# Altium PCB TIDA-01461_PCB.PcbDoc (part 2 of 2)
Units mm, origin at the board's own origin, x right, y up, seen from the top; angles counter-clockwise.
Board outline 92.5 x 57.5 mm, 4 copper layers (Top Layer, Mid Layer 1, Mid Layer 2, Bottom Layer), stack 1.54 mm thick; 150 components, 62 nets, 436 pads, 169 vias.
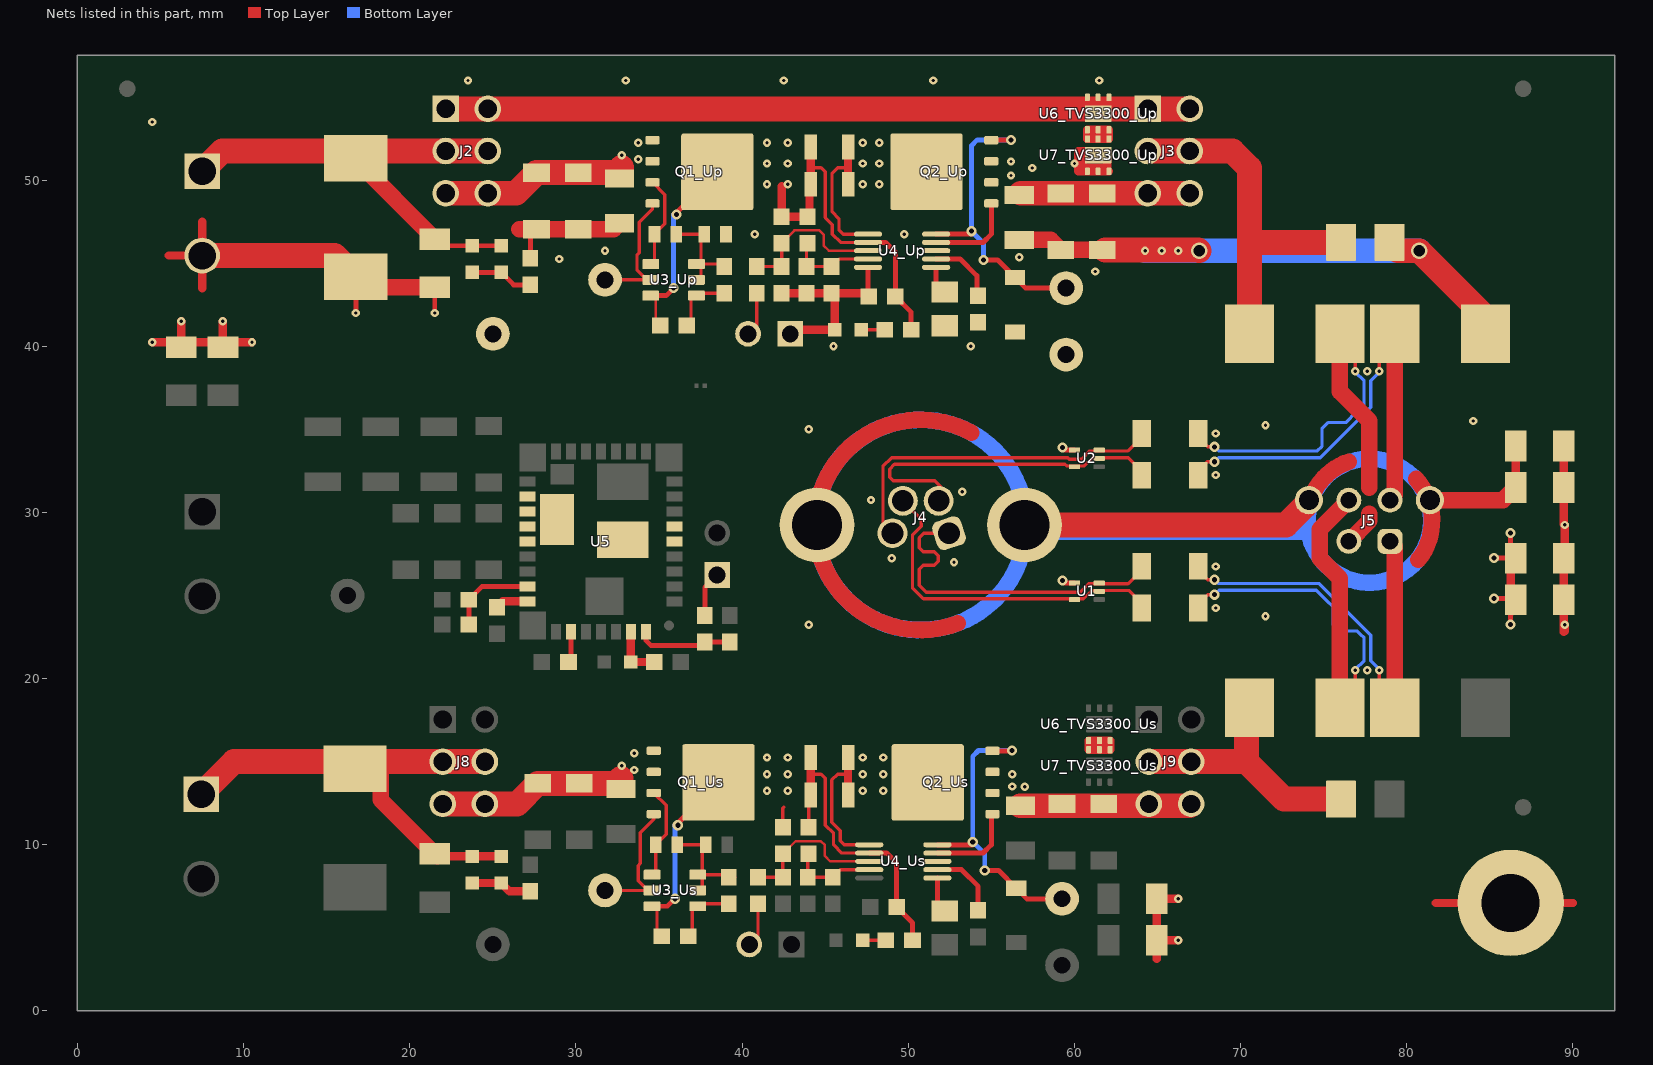
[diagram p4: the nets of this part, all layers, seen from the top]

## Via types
v1: diameter 0.5, hole 0.2, Top Layer to Bottom Layer, 134 vias
v2: diameter 0.61, hole 0.305, Top Layer to Bottom Layer, 15 vias
v3: diameter 0.6, hole 0.3, Top Layer to Bottom Layer, 6 vias
v4: diameter 0.5, hole 0.3, Top Layer to Bottom Layer, tented both sides, 6 vias
v5: diameter 1, hole 0.5, Top Layer to Bottom Layer, 6 vias
v6: diameter 1, hole 0.7, Top Layer to Bottom Layer, 2 vias

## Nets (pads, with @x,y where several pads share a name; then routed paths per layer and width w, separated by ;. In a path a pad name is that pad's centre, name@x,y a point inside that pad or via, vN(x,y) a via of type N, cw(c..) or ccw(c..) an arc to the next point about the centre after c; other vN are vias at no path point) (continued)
GND_Up: C1.1 C2.2 C11.1 C13_Up.2 C14_Up.2 C15_Up.2 C16_Up.2 C17_Up.2 C18_Up.2 C20_Up.2 C21_Up.2 C22_Up.2 D1.2 D8_Up.1 D9_Up.1 D10_Up.2 J1.2 J10_Up.1 L2.1 R1.1 R5.2 R14_Up.1 R15_Up.1 R16_Up.1 TP4.1 TP5.1 U4_Up.5 U7_TVS3300_Up.1 U7_TVS3300_Up.2 U7_TVS3300_Up.3 U7_TVS3300_Up.7@61.425,51.5 | length 97.3
  Top Layer w0.3: v1(16.75,42) D1.2@16.75,42.918 ; D1.2@16.75,44.182 D1.2@17.382,43.55 ; v1(21.5,42) C1.1@21.5,43.55 ; R1.1@27.25,45.3 27.25,47.05 C13_Up.2@27.625,47.05 ; C22_Up.2@47.575,43.2 U4_Up.5@47.575,44.75
  Top Layer w0.5: v1(4.5,40.25) C11.1@6.25,40.25 ; 5.5,45.46 J1.2@7.5,45.46 ; v1(6.25,41.5) C11.1@6.25,40.25 ; 7.5,43.5 J1.2@7.5,45.46 ; 7.5,47.5 J1.2@7.5,45.46 ; R5.2@8.75,39.95 R5.2@8.75,40.25 ; v1(8.75,41.5) R5.2@8.75,40.25 ; v1(10.5,40.25) R5.2@8.75,40.25 ; R14_Up.1@42.375,43.2 C20_Up.2@45.575,43.2 ; J10_Up.1@42.895,40.75 42.895,41 D8_Up.1@45.575,41 C20_Up.2@45.575,43.2 ; C20_Up.2@45.375,43.2 C20_Up.2@45.575,43.2 ; C22_Up.2@47.575,43.2 C20_Up.2@45.575,43.2 ; U7_TVS3300_Up.7@61,51.75 60.225,51.75 60.225,50.75 ; U7_TVS3300_Up.3@62.075,50.525 U7_TVS3300_Up.2@61.425,50.525 U7_TVS3300_Up.1@60.775,50.525 60.225,50.525 60.225,50.75 ; C11.1@6.25,40.25 C11.1@6.25,39.95 C11.1@6.25,40.25 ; C11.1@6.25,40.25 R5.2@8.75,40.25 ; 60.225,50.75 60.5,50.75 ; 60.5,50.75 60.5,51.5 v1(60.875,51.5) U7_TVS3300_Up.7@61.425,51.5 v1(61.975,51.5) 61.975,50.75 60.5,50.75
  Top Layer w1: D1.2@17.382,43.55 C1.1@21.5,43.55 ; 26.6,47.05 C13_Up.2@27.25,47.05 ; C13_Up.2@27.625,47.05 C14_Up.2@30.125,47.05 32.275,47.05 C15_Up.2@32.625,47.4 ; C16_Up.2@56.675,46.4 58.575,46.4 C17_Up.2@59.175,45.8 C18_Up.2@61.675,45.8
  Top Layer w1.5: J1.2@7.5,45.46 15.472,45.46 D1.2@16.75,44.182 ; C18_Up.2@61.85,45.8 67.45,45.8 v6(67.5,45.75) ; C2.2@78.96,46.25 79.46,45.75 v6(80.75,45.75) 84.725,41.775 L2.1@84.725,40.75
  Bottom Layer w1.5: v1(64.25,45.75) v6(80.75,45.75)
  other v1: 45.5,40 53.75,40 61.25,44.5 29,45.25 56.675,45.35 31.75,45.75 65.25,45.75 66.25,45.75 40.75,46.75 49.75,46.75 60,51 4.5,53.5 23.5,56 33,56 42.5,56 51.5,56 61.5,56
IN1_TVS3300_Up: J2.1 J2.2 J3.1 J3.2 U6_TVS3300_Up.1 U6_TVS3300_Up.2 U6_TVS3300_Up.3 U6_TVS3300_Up.7@61.425,54 | length 44.8
  Top Layer w1.5: J2.1@22.155,54.29 J2.2@24.695,54.29 J3.1@64.405,54.29 J3.2@66.945,54.29
  other v1: 60.875,54 61.975,54
NetC19_Up_1: C19_Up.1 R9_Up.1 U3_Up.1 | length 4.4
  Top Layer w0.2: R9_Up.1@36.675,41.25 36.925,41.25 36.925,43.05 U3_Up.1@37.25,43.05 37.25,43.2 C19_Up.1@39.125,43.2
NetC19_Up_2: C19_Up.2 D7_Up.2 D9_Up.2 U3_Up.2 U3_Up.3 | length 6.2
  Top Layer w0.2: D7_Up.2@36.025,46.75 D9_Up.2@37.525,46.75 ; U3_Up.2@37.25,44 37.525,44 U3_Up.3@37.525,44.95 ; D9_Up.2@37.725,46.75 37.525,46.55 U3_Up.3@37.525,44.95 ; C19_Up.2@39.125,44.95 U3_Up.3@37.525,44.95
NetC19_Us_1: C19_Us.1 R9_Us.1 U3_Us.1 | length 4.4
  Top Layer w0.2: R9_Us.1@36.75,4.5 37,4.5 37,6.3 U3_Us.1@37.325,6.3 37.325,6.45 C19_Us.1@39.2,6.45
NetC19_Us_2: C19_Us.2 D7_Us.2 D9_Us.2 U3_Us.2 U3_Us.3 | length 6.8
  Top Layer w0.2: D7_Us.2@36.1,10 37.6,10 U3_Us.3@37.6,8.2 ; U3_Us.2@37.325,7.25 37.6,7.25 U3_Us.3@37.6,8.2 ; U3_Us.3@37.325,8.2 U3_Us.3@37.6,8.2 ; C19_Us.2@39.2,8.05 C19_Us.2@39.551,8.05 ; C19_Us.2@39.2,8.2 U3_Us.3@37.6,8.2
NetC20_Up_1: C20_Up.1 R12_Up.1 R15_Up.2 U4_Up.4 | length 5.2
  Top Layer w0.2: R12_Up.1@43.875,46.15 R15_Up.2@43.875,44.8 C20_Up.1@45.375,44.8 45.825,45.25 U4_Up.4@47.575,45.25
NetC20_Us_1: C20_Us.1 R12_Us.1 R15_Us.2 U4_Us.4 | length 5.2
  Top Layer w0.2: R12_Us.1@43.95,9.4 R15_Us.2@43.95,8.05 C20_Us.1@45.45,8.05 45.9,8.5 U4_Us.4@47.65,8.5
NetC21_Up_1: C21_Up.1 U4_Up.6 | length 1.5
  Top Layer w0.3: C21_Up.1@51.675,43.216 U4_Up.6@51.675,44.75
NetC21_Us_1: C21_Us.1 U4_Us.6 | length 2.2
  Top Layer w0.3: U4_Us.6@51.75,8 51.75,6.466 C21_Us.1@52.2,6.016
NetC22_Up_1: C22_Up.1 Q1_Up.5 Q1_Up.6 Q1_Up.7 Q1_Up.8 Q1_Up.9@38.505,50.5 R7_Up.1 R8_Up.1 R9_Up.2 R10_Up.2 R11_Up.2 R12_Up.2 U3_Up.6 U4_Up.2 | length 33.6
  Top Layer w0.152: U3_Up.6@34.8,43.05 34.8,41.25 R9_Up.2@35.075,41.25
  Top Layer w0.2: 44.25,50.75 44.75,50.75 45,50.5 45,47.75 45.425,47.325 45.425,46.75 45.925,46.25 U4_Up.2@47.575,46.25
  Top Layer w0.3: U3_Up.6@34.5,43.05 34.8,43.05 35.425,43.05 v2(35.875,43.5) ; v2(36.052,47.926) 36,47.977 36,47.995 Q1_Up.9@38.505,50.5 ; U4_Up.2@47.575,46.25 48.625,46.25 49.225,45.65 C22_Up.1@49.225,43 50.175,42.05 R10_Up.2@50.175,41
  Top Layer w0.5: 42.375,49.625 R11_Up.2@42.375,47.8 R12_Up.2@43.925,47.8 44.05,47.925 R8_Up.1@44.05,49.75 ; R8_Up.1@44.125,49.75 R7_Up.1@44.125,52
  Bottom Layer w0.3: v2(35.875,43.5) v2@35.875,47.925 ; v2@35.876,47.926 v2(36.052,47.926)
  other v1: 41.5,49.75 42.75,49.75 41.5,51 42.75,51 41.5,52.25 42.75,52.25
NetC22_Us_1: C22_Us.1 Q1_Us.5 Q1_Us.6 Q1_Us.7 Q1_Us.8 Q1_Us.9@38.58,13.75 R7_Us.1 R8_Us.1 R9_Us.2 R10_Us.2 R11_Us.2 R12_Us.2 U3_Us.6 U4_Us.2 | length 31.7
  Top Layer w0.152: U3_Us.6@34.875,6.3 34.875,4.5 R9_Us.2@35.15,4.5
  Top Layer w0.2: R11_Us.2@42.45,11.05 42.45,12.2 42.5,12.25 ; R12_Us.2@44,11.05 44,12.875 R7_Us.1@44.125,13 ; 44.25,14.25 44.75,14.25 45,14 45,11.184 45.5,10.684 45.5,10 46,9.5 U4_Us.2@47.65,9.5
  Top Layer w0.3: U3_Us.6@34.575,6.3 34.875,6.3 35.5,6.3 v2(35.95,6.75) ; v2(36.127,11.176) 36.075,11.227 36.075,11.245 Q1_Us.9@38.58,13.75 ; U4_Us.2@47.65,9.5 48.7,9.5 49.3,8.9 C22_Us.1@49.3,6.25 50.25,5.3 R10_Us.2@50.25,4.25
  Top Layer w0.5: R7_Us.1@44.125,13 R8_Us.1@44.125,15.25
  Bottom Layer w0.3: v2(35.95,6.75) v2@35.95,11.175 ; v2@35.951,11.176 v2(36.127,11.176)
  other v1: 41.5,13.25 42.75,13.25 41.5,14.25 42.75,14.25 41.5,15.25 42.75,15.25
NetC27_1: C27.1 U5.28 | length 2
  Top Layer w0.5: C27.1@25.25,24.3 25.6,24.65 U5.28@27.075,24.65
NetD2_1: D2.1 D3.2 R1.2 | length 3.8
  Top Layer w0.3: D3.2@23.75,44.45 D2.1@25.5,44.45 26.25,43.7 R1.2@27.25,43.7
NetD4_1: D4.1 D5.2 R6.1 | length 3.7
  Top Layer w0.5: D5.2@23.75,7.7 D4.1@25.5,7.7 26,7.2 R6.1@27.25,7.2
NetD8_Up_2: D8_Up.2 R10_Up.1 | length 1.4
  Top Layer w0.2: D8_Up.2@47.175,41 R10_Up.1@48.575,41
NetD8_Us_2: D8_Us.2 R10_Us.1 | length 1.4
  Top Layer w0.2: D8_Us.2@47.25,4.25 R10_Us.1@48.65,4.25
NetD10_Up_1: D10_Up.1 Q2_Up.4 TP7_Up.1 U4_Up.10 | length 18.9
  Top Layer w0.3: U4_Up.10@51.675,46.75 53.8,46.75 53.8,46.923 v2(53.803,46.925) ; v2(54.525,45.2) 55.362,45.2 D10_Up.1@56.425,44.137 57.062,43.5 TP7_Up.1@59.497,43.496 ; Q2_Up.4@54.995,52.405 56.155,52.405 v2(56.175,52.425)
  Bottom Layer w0.3: v2(54.525,45.2) 54.525,46.203 v2(53.803,46.925) 53.803,52.078 54.15,52.425 v2(56.175,52.425)
NetD10_Us_1: D10_Us.1 Q2_Us.4 TP7_Us.1 U4_Us.10 | length 18.5
  Top Layer w0.3: U4_Us.10@51.75,10 53.875,10 53.875,10.173 v2(53.878,10.175) ; v2(54.6,8.45) 55.437,8.45 D10_Us.1@56.5,7.388 57.138,6.75 58.75,6.75 TP7_Us.1@59.25,6.75 ; Q2_Us.4@55.07,15.655 56.23,15.655 v2(56.25,15.675)
  Bottom Layer w0.3: v2(54.6,8.45) 54.6,9.453 v2(53.878,10.175) 53.878,15.328 54.225,15.675 v2(56.25,15.675)
NetJ10_Up_2: J10_Up.2 R13_Up.1 | length 2.7
  Top Layer w0.2: J10_Up.2@40.355,40.75 40.875,41.27 R13_Up.1@40.875,43.2
NetJ10_Us_2: J10_Us.2 R13_Us.1 | length 2.7
  Top Layer w0.2: J10_Us.2@40.43,4 40.95,4.52 R13_Us.1@40.95,6.45
NetJ11_1: J11.1 R19.1 | length 2.7
  Top Layer w0.3: R19.1@37.75,23.8 37.75,25.48 J11.1@38.5,26.23
NetQ1_Up_4: Q1_Up.4 TP6_Up.1 U3_Up.5 | length 8
  Top Layer w0.2: TP6_Up.1@31.75,44 U3_Up.5@34.25,44 ; U3_Up.5@34.5,44 U3_Up.5@34.25,44 ; Q1_Up.4@34.605,48.595 34.605,48.28 33.8,47.475 33.8,45.625 33.675,45.5 33.675,44.575 U3_Up.5@34.25,44
NetQ1_Us_4: Q1_Us.4 TP6_Us.1 U3_Us.5 | length 8
  Top Layer w0.2: TP6_Us.1@31.75,7.25 U3_Us.5@34.325,7.25 ; U3_Us.5@34.575,7.25 U3_Us.5@34.325,7.25 ; Q1_Us.4@34.68,11.845 34.68,11.53 33.875,10.725 33.875,8.875 33.75,8.75 33.75,7.825 U3_Us.5@34.325,7.25
NetQ2_Up_5: Q2_Up.5 Q2_Up.6 Q2_Up.7 Q2_Up.8 Q2_Up.9@51.095,50.5 R7_Up.2 R8_Up.2 U4_Up.1 | length 8.7
  Top Layer w0.2: 46.25,50.75 45.75,50.75 45.408,50.408 45.408,48.092 45.825,47.675 45.825,47 46.075,46.75 U4_Up.1@47.575,46.75
  Top Layer w0.5: R8_Up.2@46.375,49.75 R7_Up.2@46.375,52
  other v1: 47.25,49.75 48.25,49.75 47.25,51 48.25,51 47.25,52.25 48.25,52.25
NetQ2_Us_5: Q2_Us.5 Q2_Us.6 Q2_Us.7 Q2_Us.8 Q2_Us.9@51.17,13.75 R7_Us.2 R8_Us.2 U4_Us.1 | length 9
  Top Layer w0.2: 46.25,14.25 45.75,14.25 45.4,13.9 45.4,11.35 45.9,10.85 45.9,10.25 46.15,10 U4_Us.1@47.65,10
  Top Layer w0.5: R7_Us.2@46.375,13 R8_Us.2@46.375,15.25
  other v1: 47.25,13.25 48.5,13.25 47.25,14.25 48.5,14.25 47.25,15.25 48.5,15.25
NetR11_Up_1: R11_Up.1 R13_Up.2 R14_Up.2 U4_Up.3 | length 9.3
  Top Layer w0.15: R11_Up.1@42.375,46.2 43.15,46.975 44.65,46.975 44.9,46.725 44.9,46.075 45.225,45.75 U4_Up.3@47.575,45.75
  Top Layer w0.2: R13_Up.2@40.875,44.8 R14_Up.2@42.375,44.8 R11_Up.1@42.375,46.2
NetR11_Us_1: R11_Us.1 R13_Us.2 R14_Us.2 U4_Us.3 | length 9.3
  Top Layer w0.15: R11_Us.1@42.45,9.45 43.225,10.225 44.725,10.225 44.975,9.975 44.975,9.325 45.3,9 U4_Us.3@47.65,9
  Top Layer w0.2: R13_Us.2@40.95,8.05 R14_Us.2@42.45,8.05 R11_Us.1@42.45,9.45
NetR16_Up_2: R16_Up.2 U4_Up.7 | length 4.3
  Top Layer w0.3: U4_Up.7@51.675,45.25 53.125,45.25 54.125,44.25 R16_Up.2@54.125,42.8
NetR16_Us_2: R16_Us.2 U4_Us.7 | length 4.3
  Top Layer w0.3: U4_Us.7@51.75,8.5 53.2,8.5 54.2,7.5 R16_Us.2@54.2,6.05
NetR17_1: R17.1 R21.2 U5.27 | length 5.4
  Top Layer w0.3: R21.2@23.55,23.25 R17.1@23.55,24.75 24.35,25.55 U5.27@27.075,25.55
NetR18_2: R18.2 R19.2 U5.36 | length 5.8
  Top Layer w0.3: U5.36@34.2,22.825 34.2,22.3 34.5,22 37.55,22 R19.2@37.75,22.2 R18.2@39.25,22.2
NetR22_2: R22.2 U5.31 | length 2.1
  Top Layer w0.3: R22.2@29.55,20.75 29.7,20.9 U5.31@29.7,22.825
NetU6_TVS3300_Up_4: U6_TVS3300_Up.4 U6_TVS3300_Up.5 U6_TVS3300_Up.6 U7_TVS3300_Up.4 U7_TVS3300_Up.5 U7_TVS3300_Up.6 | length 5
  Top Layer w0.5: U6_TVS3300_Up.4@60.775,53.025 U6_TVS3300_Up.5@61.425,53.025 U6_TVS3300_Up.6@62.075,53.025 U7_TVS3300_Up.4@62.075,52.475 U7_TVS3300_Up.5@61.425,52.475 U7_TVS3300_Up.6@60.775,52.475 60.75,52.475 60.75,52.95 61.75,52.95 61.75,52.55
NetU6_TVS3300_Us_4: U6_TVS3300_Us.4 U6_TVS3300_Us.5 U6_TVS3300_Us.6 U7_TVS3300_Us.4 U7_TVS3300_Us.5 U7_TVS3300_Us.6 | length 4.9
  Top Layer w0.5: U6_TVS3300_Us.4@60.85,16.275 U6_TVS3300_Us.5@61.5,16.275 U6_TVS3300_Us.6@62.15,16.275 U6_TVS3300_Us.6@62.15,16.2 ; U6_TVS3300_Us.6@62.15,16.2 U7_TVS3300_Us.4@62.15,15.725 U7_TVS3300_Us.5@61.5,15.725 U7_TVS3300_Us.6@60.85,15.725 60.85,16.2 U6_TVS3300_Us.6@62.15,16.2
PE: C5.1 C8.1 C9.1 MH1.1 R2.2 R3.2 R4.2 | length 26.6
  Top Layer w0.5: 64.95,3.125 C9.1@64.95,4.25 ; v1(66.25,4.25) C9.1@64.95,4.25 ; v1(66.25,6.75) R4.2@64.95,6.75 C9.1@64.95,4.25 ; 81.75,6.5 MH1.1@86.25,6.5 ; v1(89.5,23.25) 89.5,22.85 89.45,22.8 C5.1@89.45,24.75 R2.2@89.45,27.25 89.5,27.3 v1(89.5,29.25) 89.45,29.3 C8.1@89.45,31.5 R3.2@89.45,34 R3.2@89.5,33.95 ; 90,6.5 MH1.1@86.377,6.5 ; MH1.1@86.25,6.5 86.25,6.373 86.377,6.373 MH1.1@86.377,6.5 ; MH1.1@86.25,6.5 MH1.1@86.377,6.5
PH: U5.6 U5.7 U5.21 U5.22 U5.23 U5.24 U5.38 U5.41
PWR_in_Up: C13_Up.1 C14_Up.1 C15_Up.1 D7_Up.1 J2.5 J2.6 Q1_Up.1 Q1_Up.2 Q1_Up.3 U3_Up.4 | length 16.8
  Top Layer w0.2: U3_Up.4@34.5,44.95 34.725,45.175 D7_Up.1@34.725,46.75 35.35,47.375 35.35,49.12 Q1_Up.3@34.605,49.865
  Top Layer w1.5: J2.5@22.155,49.21 J2.6@24.695,49.21 26.385,49.21 C13_Up.1@27.625,50.45 C14_Up.1@30.125,50.45 32.45,50.45 32.75,50.75
  other v1: 33.75,51.25 32.75,51.5 33.75,52.25
PWR_in_Us: C13_Us.1 C14_Us.1 C15_Us.1 D7_Us.1 J8.5 J8.6 Q1_Us.1 Q1_Us.2 Q1_Us.3 U3_Us.4 | length 16.9
  Top Layer w0.2: U3_Us.4@34.575,8.2 34.8,8.425 D7_Us.1@34.8,10 35.425,10.625 35.425,12.37 Q1_Us.3@34.68,13.115
  Top Layer w1.5: J8.5@21.98,12.46 J8.6@24.52,12.46 26.46,12.46 C13_Us.1@27.7,13.7 C14_Us.1@30.2,13.7 32.4,13.7 32.7,14
  other v1: 33.5,14.5 32.75,14.75 33.5,15.5
PWRGD: D11.2 R20.1 U5.35 | length 3.2
  Top Layer w0.5: U5.35@33.3,22.825 D11.2@33.3,21 R20.1@34.7,21
RXE_N: C6.2 J4.3 U2.3 | length 20.9
  Top Layer w0.2: J4.3@49.05,28.75 48.475,29.325 48.475,32.775 49,33.3 59.591,33.3 59.691,33.2 60.425,33.2 60.925,33.7 61.49,33.7 63.225,33.7 64.05,34.525 C6.2@64.05,34.75
RXE_P: C3.2 J4.2 U2.2 U2.5 | length 20.9
  Top Layer w0.2: J4.2@51.825,30.7 52,30.875 52,31.5 51.6,31.9 49.1,31.9 48.875,32.125 48.875,32.609 49.166,32.9 59.425,32.9 59.525,32.8 60.591,32.8 61.091,33.3 61.49,33.3 63.25,33.3 64.05,32.5 C3.2@64.05,32.25
RXEP_N: C6.1 J5.3 L1.2 | length 29.4
  Top Layer w0.2: C6.1@67.45,34.75 67.45,34.525 68.025,33.95 v2(68.425,33.95) ; L1.2@75.975,40.75 76.9,39.825 v1(76.9,38.5)
  Top Layer w1: L1.2@75.975,40.75 75.975,37.275 77.75,35.5 77.75,31.5 ; J5.3@76.51,28.26 77.75,29.5 77.75,29.929
  Bottom Layer w0.2: v2(68.425,33.95) 68.675,33.7 74.525,33.7 74.625,33.7 74.892,33.967 74.892,34.508 74.892,35.051 75.254,35.413 75.797,35.413 76.338,35.413 76.972,36.047 77.425,36.5 77.425,37.922 76.9,38.447 v1(76.9,38.5)
RXEP_P: C3.1 J5.2 L2.2 | length 27.4
  Top Layer w0.2: C3.1@67.45,32.25 67.45,32.5 68,33.05 v2(68.425,33.05) ; v1(78.35,38.5) 78.35,39.825 L2.2@79.275,40.75
  Top Layer w1: J5.2@78.99,30.74 79.275,31.025 L2.2@79.275,40.75
  Bottom Layer w0.2: v2(68.425,33.05) 68.675,33.3 74.791,33.3 77.825,36.334 77.825,37.922 78.35,38.447 v1(78.35,38.5)
Shield: C8.2 J4.S1 J4.S2 J5.S1 J5.S2 R3.1 | length 140.5
  Top Layer w0.5: C8.2@86.55,31.5 R3.1@86.55,34
  Top Layer w1: J4.S2@44.425,29.201 ccw(c50.75,29.25) 52.971,23.328 ; J4.S2@44.425,29.306 cw(c50.75,29.25) 53.779,34.803 ; J5.S2@74.046,30.187 cw(c77.75,29.5) 74.184,30.715 cw(c77.75,29.5) 76.508,33.057 ; 80.56,32.009 cw(c77.75,29.5) 80.699,27.156 ; J5.S1@81.39,30.74 85.79,30.74 C8.2@86.55,31.5
  Top Layer w1.5: J4.S1@57,29.25 72.719,29.25 J5.S2@74.184,30.715
  Bottom Layer w1: J4.S1@56.25,29.25 J4.S1@56.4,29.25 ; J4.S1@57.072,29.441 ccw(c50.75,29.25) J4.S1@57.075,29.194 ; 81.475,29.5 ccw(c77.75,29.5) 81.475,29.5
  Bottom Layer w1.5: J4.S1@56.6,29.1 57.073,29.1 73.9,29.1
TXE_N: C7.2 J4.4 U1.2 U1.5 | length 20.8
  Top Layer w0.2: J4.4@49.675,30.7 50.775,29.6 50.775,29.158 50.25,28.633 50.25,25.459 50.909,24.8 52.3,24.8 59.96,24.8 U1.5@60.01,24.75 60.06,24.8 60.525,24.8 61.025,25.3 63.3,25.3 64.05,24.55 C7.2@64.05,24.25
TXE_P: C4.2 J4.1 U1.3 | length 20.8
  Top Layer w0.2: J4.1@52.45,28.75 50.933,28.75 50.65,28.467 50.65,28.35 50.65,27.865 50.89,27.625 51.56,27.625 51.8,27.385 51.8,27.065 51.56,26.825 50.89,26.825 50.65,26.585 50.65,26.025 50.65,25.625 51.075,25.2 52.466,25.2 60.359,25.2 60.859,25.7 63.225,25.7 64.05,26.525 C4.2@64.05,26.75
TXEP_N: C7.1 J5.4 L4.2 | length 30.9
  Top Layer w0.2: C7.1@67.45,24.25 67.45,24.475 68.025,25.05 v2(68.425,25.05) ; L4.2@75.975,18.25 76.9,19.175 v1(76.9,20.5)
  Top Layer w1: L4.2@75.975,18.25 75.975,26.025 74.75,27.25 74.75,28.98 J5.4@76.51,30.74
  Bottom Layer w0.2: v2(68.425,25.05) 68.7,25.325 74.55,25.325 75.188,24.687 75.564,24.311 75.564,23.768 75.562,23.767 75.562,23.223 75.924,22.861 76.467,22.861 76.469,22.863 77.012,22.863 77.193,22.682 77.425,22.45 77.425,21.078 76.9,20.553 v1(76.9,20.5)
TXEP_P: C4.1 J5.1 L3.2 | length 27.3
  Top Layer w0.2: C4.1@67.45,26.75 67.45,26.525 68.025,25.95 v2(68.425,25.95) ; v1(78.35,20.5) 78.35,19.175 L3.2@79.275,18.25
  Top Layer w1: J5.1@78.99,28.26 79.275,27.975 L3.2@79.275,18.25
  Bottom Layer w0.2: v2(68.425,25.95) 68.65,25.725 74.716,25.725 77.825,22.616 77.825,21.078 78.35,20.553 v1(78.35,20.5)
UP: C1.2 D1.1 D2.2 D3.1 J1.1 J2.3 J2.4 | length 28.7
  Top Layer w0.3: C1.2@21.5,46.45 21.9,46.05 D3.1@23.75,46.05 D2.2@25.5,46.05
  Top Layer w1: D1.1@16.75,51.319 16.75,51.2 C1.2@21.5,46.45
  Top Layer w1.5: J1.1@7.5,50.54 8.71,51.75 J2.3@22.155,51.75 J2.4@24.695,51.75
Up_InOut: C2.1 J3.3 J3.4 L1.1 | length 22
  Top Layer w1.5: J3.3@64.405,51.75 J3.4@66.945,51.75 69.5,51.75 70.525,50.725 70.525,46.25 ; L1.1@70.525,40.75 70.525,46.25 ; C2.1@76.04,46.25 70.525,46.25
UP_PGD: U4_Up.8
UP_PROTECTED: C16_Up.1 C17_Up.1 C18_Up.1 J3.5 J3.6 Q2_Up.1 Q2_Up.2 Q2_Up.3 U4_Up.9 | length 15.5
  Top Layer w0.3: U4_Up.9@51.675,46.25 54.5,46.25 55,46.75 55,48.59 Q2_Up.1@54.995,48.595
  Top Layer w1.5: C16_Up.1@56.785,49.21 J3.5@64.405,49.21 J3.6@66.945,49.21
  other v1: 56.175,50.275 57.45,50.725 56.175,51.125
US: C12.1 D4.2 D5.1 D6.2 J7.1 J8.3 J8.4 | length 28.6
  Top Layer w0.5: C12.1@21.5,9.3 21.65,9.3 D4.2@25.5,9.3
  Top Layer w1: D6.2@18.25,14.568 18.25,12.7 C12.1@21.5,9.45 C12.1@21.65,9.3
  Top Layer w1.5: J7.1@7.45,13.04 9.41,15 J8.3@21.98,15 J8.4@24.52,15
Us_InOut: C10.1 J9.3 J9.4 L4.1 | length 15.8
  Top Layer w1.5: J9.3@64.48,15 J9.4@67.02,15 70.35,15 ; L4.1@70.525,18.25 70.35,18.075 70.35,15 ; C10.1@76.04,12.75 72.6,12.75 70.35,15
US_PGD: U4_Us.8
Us_protected: C16_Us.1 C17_Us.1 C18_Us.1 J9.5 J9.6 Q2_Us.1 Q2_Us.2 Q2_Us.3 U4_Us.9 | length 15.6
  Top Layer w0.3: U4_Us.9@51.75,9.5 54.5,9.5 55,10 55,11.775 Q2_Us.1@55.07,11.845
  Top Layer w1.5: C16_Us.1@56.75,12.35 66.91,12.35 J9.6@67.02,12.46
  other v1: 57,13.5 56.25,13.504 56.25,14.25
VGND: C5.2 R2.1 U1.4 U2.4 | length 9.3
  Top Layer w0.3: v3(59.275,25.9) 59.425,25.75 U1.4@60.01,25.75 ; v3(59.275,33.9) 59.425,33.75 U2.4@60.01,33.75 ; v3@85.101,27.351 85.203,27.25 v3(85.25,27.25) 86.25,27.25 R2.1@86.3,27.25 ; v3(85.25,24.832) C5.2@86.25,24.832 ; v3(86.25,23.25) C5.2@86.25,24 ; R2.1@86.25,27.55 v3(86.25,28.75)
  Top Layer w0.5: C5.2@86.25,24 86.25,24.832 86.25,27.25 R2.1@86.25,27.55
  other v1: 77.625,20.5 44,23.25 71.5,23.75 68.5,24.25 68.5,26.75 52.75,27 49,27.25 47.75,30.75 53.25,31.25 68.5,32.25 68.5,34.75 44,35 71.5,35.25 84,35.5 77.625,38.5
pads on no net: FID1.1 FID2.1 FID3.1 LBL1.0 Q1_Up.9@37.245,49.03 Q1_Up.9@37.245,50.5 Q1_Up.9@37.245,51.97 Q1_Up.9@38.925,49.03 Q1_Up.9@38.925,50.5 Q1_Up.9@38.925,51.97 Q1_Us.9@37.32,12.28 Q1_Us.9@37.32,13.75 Q1_Us.9@37.32,15.22 Q1_Us.9@39,12.28 Q1_Us.9@39,13.75 Q1_Us.9@39,15.22 Q2_Up.9@50.675,49.03 Q2_Up.9@50.675,50.5 Q2_Up.9@50.675,51.97 Q2_Up.9@52.355,49.03 Q2_Up.9@52.355,50.5 Q2_Up.9@52.355,51.97 Q2_Us.9@50.75,12.28 Q2_Us.9@50.75,13.75 Q2_Us.9@50.75,15.22 Q2_Us.9@52.43,12.28 Q2_Us.9@52.43,13.75 Q2_Us.9@52.43,15.22 SH-J1.0 SH-J2.0 SH-J3.0 SH-J4.0 SH-J5.0 SH-J6.0 SH-J7.0 SH-J8.0 SH-J9_Up.0 SH-J9_Us.0 SH-J10.0 U1.1 U2.1 U5.2 U5.3 U5.25 U6_TVS3300_Up.7@60.975,54 U6_TVS3300_Up.7@61.875,54 U6_TVS3300_Us.7@61.05,17.25 U6_TVS3300_Us.7@61.95,17.25 U7_TVS3300_Up.7@60.975,51.5 U7_TVS3300_Up.7@61.875,51.5 U7_TVS3300_Us.7@61.05,14.75 U7_TVS3300_Us.7@61.95,14.75
copper on no net:
  other v5: 86.25,4.025 84.107,5.263 88.393,5.263 84.107,7.737 88.393,7.737 86.25,8.975

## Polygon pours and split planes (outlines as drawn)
RXEP_N on Top Layer "TOP_LAYER_RXEP_N_P233" (solid, pour order 233): 77.247,29.75 77.325,30.538 77.325,31.038 77.247,31.75 78.251,31.75 78.125,31.038 78.125,30.538 78.251,29.75
PE on Top Layer "TOP_LAYER_PE_P257" (solid, remove dead copper, pour order 257): 64.5,2.5 64.25,2.75 64.25,7.75 82,7.75 84.5,10.25 88.25,10.25 88.75,10.75 88.75,35 90.25,35 90.5,34.75 90.5,2.75 90.25,2.5
VGND on Top Layer "TOP_LAYER_VGND_P256" (solid, remove dead copper, pour order 256): 69.75,11.25 70,11 87,11.001 87.25,11.25 87.25,48 87,48.25 70,48.25 69.75,48 69.75,37 69.5,36.75 42.75,36.75 42.5,36.5 42.5,22 42.75,21.75 69.5,21.75 69.75,21.5
AGND on Top Layer "TOP_LAYER_AGND_P244" (solid, remove dead copper, pour order 244): 27.75,24.5 27.75,27.75 36.5,27.75 36.5,29.75 37.75,29.75 37.75,37.75 41,37.75 41.25,37.5 41.25,27.75 41.25,22.25 26.5,22.25 26.5,24.5
PH on Top Layer "TOP_LAYER_PH_P241" (solid, pour order 241): 36.5,27.75 34.5,27.75 34.5,27.25 31.25,27.25 31.25,28 26.5,28 26.5,31.25 30,31.25 30,29.5 36.5,29.5
BUCK_OUT on Top Layer "TOP_LAYER_BUCK_OUT_P245" (solid, remove dead copper, pour order 245): 31.25,30.75 31.25,34.5 25.75,34.5 25.5,34.75 25.5,35.75 36.5,35.75 36.5,31.5 34.5,31.5 34.5,30.75 31.37,30.75 31.37,30.89
PWR_in_Us on Top Layer "TOP_LAYER_PWR_IN_US_P234" (solid, remove dead copper, pour order 234): 35.25,12.75 31.75,12.75 31.75,14.25 32.75,16 35.25,16
NetC22_Us_1 on Top Layer "TOP_LAYER_NETC22_US_1_P235" (solid, remove dead copper, pour order 235): 39.75,11.5 41.5,11.5 41.5,11.75 44.5,11.75 44.5,16 39.75,16
NetQ2_Us_5 on Top Layer "TOP_LAYER_NETQ2_US_5_P236" (solid, remove dead copper, pour order 236): 50,11.5 46,11.5 46,16 50,16
Us_protected on Top Layer "TOP_LAYER_US_PROTECTED_P237" (solid, remove dead copper, pour order 237): 54.5,14.75 54.5,11.5 55.525,11.5 55.775,11.75 58.25,11.75 58.25,14.5 58,14.75
UP_PROTECTED on Top Layer "TOP_LAYER_UP_PROTECTED_P242" (solid, remove dead copper, pour order 242): 54.5,51.5 54.5,48.25 55.525,48.25 55.775,48.5 58.25,48.5 58.25,51.25 58,51.5
NetQ2_Up_5 on Top Layer "TOP_LAYER_NETQ2_UP_5_P240" (solid, remove dead copper, pour order 240): 50,48.25 46,48.25 46,52.75 50,52.75
NetC22_Up_1 on Top Layer "TOP_LAYER_NETC22_UP_1_P239" (solid, remove dead copper, pour order 239): 39.75,48.25 41.5,48.25 41.5,48.5 44.5,48.5 44.5,52.75 39.75,52.75
PWR_in_Up on Top Layer "TOP_LAYER_PWR_IN_UP_P238" (solid, remove dead copper, pour order 238): 35.25,49.5 31.75,49.5 31.75,51 32.75,52.75 35.25,52.75
GND on Top Layer "TOP_LAYER_GND_P243" (solid, remove dead copper, pour order 243): 14,29.492 14,31.25 14,32.25 26.25,32.25 26.25,34.25 31.25,34.25 31.25,30.75 34.5,30.75 34.5,31.25 36.5,31.25 36.5,37.75 37.75,37.75 37.75,29.753 37.5,29.492 30.008,29.492 30,31.25 26.5,31.25 26.5,29.492
GND on Top Layer "TOP_LAYER_GND_P254" (solid, remove dead copper, pour order 254): 2.75,37.75 2.5,37.498 2.5,22.25 2.5,2.75 2.75,2.5 62.25,2.5 62.5,2.75 62.5,19.75 62.25,20 41.25,20 41.25,37.498 41,37.75
GND_Up on Top Layer "TOP_LAYER_GND_UP_P255" (solid, remove dead copper, pour order 255): 2.75,39.25 62.25,39.25 62.5,39.508 62.5,56.25 62.25,56.5 2.75,56.5 2.5,56.25 2.5,39.5
GND on Mid Layer 1 "MID_LAYER_1_GND_P266" (solid, remove dead copper, pour order 266): 2.75,37.75 2.5,37.498 2.5,22.25 2.5,2.75 2.75,2.5 62.25,2.5 62.5,2.75 62.5,19.75 62.25,20 41.25,20 41.25,37.498 41,37.75
PE on Mid Layer 1 "MID_LAYER_1_PE_P269" (solid, remove dead copper, pour order 269): 64.5,2.5 64.25,2.75 64.25,7.5 64.5,7.75 82,7.75 84.5,10.25 88.25,10.25 88.75,10.75 88.75,34.75 89,35 90.25,35 90.5,34.75 90.5,2.75 90.25,2.5
VGND on Mid Layer 1 "MID_LAYER_1_VGND_P268" (solid, remove dead copper, pour order 268): 69.75,11.25 70,11 87,11.001 87.25,11.25 87.25,48 87,48.25 70,48.25 69.75,48 69.75,37 69.5,36.75 42.75,36.75 42.5,36.5 42.5,22 42.75,21.75 69.5,21.75 69.75,21.5
GND_Up on Mid Layer 1 "MID_LAYER_1_GND_UP_P267" (solid, remove dead copper, pour order 267): 2.75,39.25 62.25,39.25 62.5,39.508 62.5,56.25 62.25,56.5 2.75,56.5 2.5,56.25 2.5,39.5
GND on Mid Layer 2 "MID_LAYER_2_GND_P262" (solid, remove dead copper, pour order 262): 2.75,37.75 2.5,37.498 2.5,22.25 2.5,2.75 2.75,2.5 62.25,2.5 62.5,2.75 62.5,19.75 62.25,20 41.25,20 41.25,37.498 41,37.75
PE on Mid Layer 2 "MID_LAYER_2_PE_P265" (solid, remove dead copper, pour order 265): 64.5,2.5 64.25,2.75 64.25,7.5 64.5,7.75 82,7.75 84.5,10.25 88.25,10.25 88.75,10.75 88.75,34.75 89,35 90.25,35 90.5,34.75 90.5,2.75 90.25,2.5
VGND on Mid Layer 2 "MID_LAYER_2_VGND_P264" (solid, remove dead copper, pour order 264): 69.75,11.25 70,11 87,11.001 87.25,11.25 87.25,48 87,48.25 70,48.25 69.75,48 69.75,37 69.5,36.75 42.75,36.75 42.5,36.5 42.5,22 42.75,21.75 69.5,21.75 69.75,21.5
GND_Up on Mid Layer 2 "MID_LAYER_2_GND_UP_P263" (solid, remove dead copper, pour order 263): 2.75,39.25 62.25,39.25 62.5,39.508 62.5,56.25 62.25,56.5 2.75,56.5 2.5,56.25 2.5,39.5
GND on Bottom Layer "BOTTOM_LAYER_GND_P258" (solid, remove dead copper, pour order 258): 2.75,37.75 2.5,37.498 2.5,22.25 2.5,2.75 2.75,2.5 62.25,2.5 62.5,2.75 62.5,19.75 62.25,20 41.25,20 41.25,37.498 41,37.75
PE on Bottom Layer "BOTTOM_LAYER_PE_P261" (solid, remove dead copper, pour order 261): 64.5,2.5 64.25,2.75 64.25,7.5 64.5,7.75 82,7.75 84.5,10.25 88.25,10.25 88.75,10.75 88.75,34.75 89,35 90.25,35 90.5,34.75 90.5,2.75 90.25,2.5
VGND on Bottom Layer "BOTTOM_LAYER_VGND_P260" (solid, remove dead copper, pour order 260): 69.75,11.25 70,11 87,11.001 87.25,11.25 87.25,48 87,48.25 70,48.25 69.75,48 69.75,37 69.5,36.75 42.75,36.75 42.5,36.5 42.5,22 42.75,21.75 69.5,21.75 69.75,21.5
GND_Up on Bottom Layer "BOTTOM_LAYER_GND_UP_P259" (solid, remove dead copper, pour order 259): 2.75,39.25 62.25,39.25 62.5,39.508 62.5,56.25 62.25,56.5 2.75,56.5 2.5,56.25 2.5,39.5
PWR_in_Us on Bottom Layer "BOTTOM_LAYER_PWR_IN_US_P249" (solid, remove dead copper, pour order 249): 35.25,12.75 31.75,12.75 31.75,14.25 32.75,16 35.25,16
NetC22_Us_1 on Bottom Layer "BOTTOM_LAYER_NETC22_US_1_P248" (solid, remove dead copper, pour order 248): 39.75,11.5 41.5,11.5 41.5,11.75 44.5,11.75 44.5,16 39.75,16
NetQ2_Us_5 on Bottom Layer "BOTTOM_LAYER_NETQ2_US_5_P247" (solid, remove dead copper, pour order 247): 50,11.5 46,11.5 46,16 50,16
Us_protected on Bottom Layer "BOTTOM_LAYER_US_PROTECTED_P246" (solid, remove dead copper, pour order 246): 54.5,14.75 54.5,11.5 55.525,11.5 55.775,11.75 58.25,11.75 58.25,14.5 58,14.75
UP_PROTECTED on Bottom Layer "BOTTOM_LAYER_UP_PROTECTED_P253" (solid, remove dead copper, pour order 253): 54.5,51.5 54.5,48.25 55.525,48.25 55.775,48.5 58.25,48.5 58.25,51.25 58,51.5
NetQ2_Up_5 on Bottom Layer "BOTTOM_LAYER_NETQ2_UP_5_P252" (solid, remove dead copper, pour order 252): 50,48.25 46,48.25 46,52.75 50,52.75
NetC22_Up_1 on Bottom Layer "BOTTOM_LAYER_NETC22_UP_1_P251" (solid, remove dead copper, pour order 251): 39.75,48.25 41.5,48.25 41.5,48.5 44.5,48.5 44.5,52.75 39.75,52.75
PWR_in_Up on Bottom Layer "BOTTOM_LAYER_PWR_IN_UP_P250" (solid, remove dead copper, pour order 250): 35.25,49.5 31.75,49.5 31.75,51 32.75,52.75 35.25,52.75

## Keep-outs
Keep-Out Layer:
  the board outline again, w0.5
  text ".Layer_Name" at 14.656,-21.806 h1.52

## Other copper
Top Layer:
  region net PE: 70,7.5 70,2.75 80,2.75 80,7.5
  pour cut-out: 12.75,22.25 41.5,22.25 41.5,20 41.25,19.75 12.75,19.75 12.5,20 12.5,22
  pour cut-out: 2.25,22.25 2.5,22.5 2.75,22.25 9.75,22.25 10,22 10,20 9.75,19.75 2.75,19.75 2.5,19.5 2.25,19.75
  text ".Layer_Name" at 14.656,-21.806 h1.52
Mid Layer 1:
  pour cut-out: 2.5,22.25 10,22.25 10,19.75 2.5,19.75
  pour cut-out: 12.5,22.25 41.5,22.25 41.5,19.75 12.5,19.75
  text ".Layer_Name" at 14.656,-21.806 h1.52
Mid Layer 2:
  pour cut-out: 2.5,22.25 10,22.25 10,19.75 2.5,19.75
  pour cut-out: 12.5,22.25 41.5,22.25 41.5,19.75 12.5,19.75
  text ".Layer_Name" at 14.656,-21.806 h1.52
Bottom Layer:
  pour cut-out: 2.5,22.25 10,22.25 10,19.75 2.5,19.75
  pour cut-out: 12.5,22.25 41.5,22.25 41.5,19.75 12.5,19.75
  text ".Layer_Name" at 14.656,-21.806 h1.52

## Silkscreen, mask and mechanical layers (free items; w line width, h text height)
Top Overlay:
  rectangle: 82.38,45.5 90,48.04
  lines w0.2: 0.75,3.75 1.15,2.55 ; 0.75,54.35 1.15,55.55 ; 0.95,2.55 1.35,2.55 ; 0.95,55.55 1.35,55.55 ; 1.15,24.897 1.15,2.55 ; 1.15,33.203 1.15,55.55 ; 1.55,3.75 1.15,2.55 ; 1.55,54.35 1.15,55.55 ; 2.5,1.3 2.5,1.7 ; 3.7,1.1 2.5,1.5 ; 3.7,1.9 2.5,1.5 ; 42.347,1.5 2.5,1.5 ; 50.653,1.5 90.5,1.5 ; 89.3,1.1 90.5,1.5 ; 89.3,1.9 90.5,1.5 ; 90.5,1.3 90.5,1.7
  text "TIDA-01461" at 73.5,54.75 h2
  text "24V Up" at 4.25,54 h2
  text "up to 3A current / use 2 jumpers" at 12,54 h1.2
  text "G-Q1" at 30.5,41.5 h1.2
  text "GNDp" at 4.25,41.25 h2
  text "G-Q2" at 58.5,41.25 h1.2
  text "J10 set: UVLO 22.5V - 23.5V / J10 open: UVLO 20.0V - 21.0V" at 40,37.25 h1.2
  text "5V (Us)" at 4.25,33.5 h2
  text "J11 set : 5V / J11 open: 12V" at 40,30.5 h1.2 r90
  text "53 (mm)" at 1.95,25.151 h1.2 r90
  text "GNDs" at 4.25,20.5 h2
  text "EtherCAT <=> EtherCAT P" at 46.25,20.25 h2
  text "24V Us" at 4.25,16.5 h2
  text "up to 3A current / use 2 jumpers" at 11.75,16.25 h1.2
  text "G-Q1" at 30.5,4.75 h1.2
  text "G-Q2" at 58,4.5 h1.2
  text "GNDs" at 4.25,3.5 h2
  text "88 (mm)" at 42.601,0.7 h1.2
  text ".Layer_Name" at 14.656,-21.806 h1
Bottom Overlay:
  text ".Layer_Name" at 14.656,-21.806 h1.52
Top Paste:
  text ".Layer_Name" at 14.656,-21.806 h1.52
Bottom Paste:
  text ".Layer_Name" at 14.656,-21.806 h1.52
Top Solder:
  text ".Layer_Name" at 14.656,-21.806 h1.52
  text ".Layer_Name" at 14.656,-21.806 h1.52
Bottom Solder:
  text ".Layer_Name" at 14.656,-21.806 h1.52
Drill Guide:
  text ".Layer_Name" at 14.656,-21.806 h1.52
M1 Board Outline:
  lines w0.254: 92.5,0 92.5,57.5
  lines w0.5: 0,0 0,57.5 92.5,57.5 92.5,0 0,0
  text ".Layer_Name" at 14.656,-21.806 h1.52
M2 Board Dimensions:
  lines w0.254: -3,1.5 -2.492,-0.024 ; -3,55.952 -2.492,57.476 ; -2.746,-0.024 -2.238,-0.024 ; -2.746,57.476 -2.238,57.476 ; -2.492,22.226 -2.492,-0.024 ; -2.492,35.226 -2.492,57.476 ; -1.984,1.5 -2.492,-0.024 ; -1.984,55.952 -2.492,57.476 ; -0.024,-2.512 -0.024,-2.004 ; 1.5,-2.766 -0.024,-2.258 ; 1.5,-1.75 -0.024,-2.258 ; 39.726,-2.258 -0.024,-2.258 ; 52.726,-2.258 92.476,-2.258 ; 90.952,-2.766 92.476,-2.258 ; 90.952,-1.75 92.476,-2.258 ; 92.476,-2.512 92.476,-2.004
  text "57.5 (mm)" at -1.578,22.48 h1.52 r90
  text "92.5 (mm)" at 39.98,-3.172 h1.52
  text ".Layer_Name" at 14.656,-21.806 h1.52
M3 3D STEP Top:
  text ".Layer_Name" at 14.656,-21.806 h1.52
M4 3D STEP Bottom:
  text ".Layer_Name" at 14.656,-21.806 h1.52
M5 Assembly Top:
  lines w0.254: -7.417,-23.626 160.223,-23.626 ; -7.417,-18.462 160.274,-18.462 ; -7.417,-13.297 -7.417,-28.791 94.31,-28.791 160.274,-28.791 160.274,-13.297 -7.404,-13.297 -7.404,-28.791 32.614,-28.791 ; 55.194,-28.791 55.194,-13.297 ; 87.376,-18.462 87.376,-13.297 ; 108.712,-18.462 108.712,-13.297 ; 124.511,-28.956 124.511,-23.804
  text "COMPONENTS MARKED 'DNP' SHOULD NOT BE POPULATED." at 29.299,-8.09 h1.52
  text "ASSEMBLY VARIANT:" at 29.286,-11.024 h1.52
  text ".VariantName" at 55.601,-11.024 h1.52
  text "PCB VIEWED FROM TOP SIDE" at -5.804,-16.654 h1.52
  text "BOARD #:" at 57.099,-16.654 h1.52
  text ".PRJ_Number" at 70.955,-16.654 h1.52
  text "REV:" at 92.405,-16.654 h1.52
  text ".PCB_Rev" at 99.809,-16.654 h1.52
  text "SVN REV:" at 113.69,-16.654 h1.52
  text ".VersionControl_RevNumber" at 126.543,-16.654 h1.52
  text "TID #:" at 57.099,-21.819 h1.52
  text ".TID" at 70.955,-21.819 h1.52
  text "PLOT NAME =" at -5.804,-27.034 h1.52
  text ".plot_File_Name" at 14.656,-27.034 h1.52
  text "GENERATED    :" at 57.15,-27.034 h1.52
  text ".Print_Date" at 79.235,-27.034 h1.52
  text ".Print_Time" at 97.752,-27.034 h1.52
  text "TEXAS INSTRUMENTS" at 129.87,-27.034 h1.52
M6 Assembly Bottom:
  lines w0.254: -7.429,-18.474 160.261,-18.474 ; -7.379,-23.639 160.261,-23.639 ; 28.334,-28.969 28.334,-23.817 ; 44.133,-18.474 44.133,-13.31 ; 65.468,-18.474 65.468,-13.31 ; 97.65,-28.804 97.65,-13.31 ; 120.231,-28.804 160.249,-28.804 160.249,-13.31 -7.429,-13.31 -7.429,-28.804 58.534,-28.804 160.261,-28.804 160.261,-13.31
  text "COMPONENTS MARKED 'DNP' SHOULD NOT BE POPULATED." at 154.991,-8.077 h1.52
  text ".VariantName" at 128.473,-11.024 h1.52
  text "ASSEMBLY VARIANT:" at 154.864,-11.024 h1.52
  text ".VersionControl_RevNumber" at 26.302,-16.667 h1.52
  text "SVN REV:" at 39.154,-16.667 h1.52
  text ".PCB_Rev" at 53.035,-16.667 h1.52
  text "REV:" at 60.439,-16.667 h1.52
  text ".PRJ_Number" at 81.89,-16.667 h1.52
  text "BOARD #:" at 95.745,-16.667 h1.52
  text "PCB VIEWED FROM BOTTOM SIDE" at 158.648,-16.667 h1.52
  text ".TID" at 81.89,-21.831 h1.52
  text "TID #:" at 95.745,-21.831 h1.52
  text "TEXAS INSTRUMENTS" at 22.974,-27.047 h1.52
  text ".Print_Time" at 55.093,-27.047 h1.52
  text ".Print_Date" at 73.609,-27.047 h1.52
  text "GENERATED    :" at 95.694,-27.047 h1.52
  text ".plot_File_Name" at 138.189,-27.047 h1.52
  text "PLOT NAME =" at 158.648,-27.047 h1.52
M9 Title Sheet:
  drawing of 57 lines, arcs and shapes, not listed
  text "1" at 18.792,204.127 h1.78
  text "2" at 82.182,204.127 h1.78
  text "3" at 145.411,204.127 h1.78
  text "4" at 209.08,204.127 h1.78
  text "5" at 272.555,204.127 h1.78
  text "6" at 336.182,204.127 h1.78
  text "A" at -10.579,175.095 h1.78
  text "A" at 365.341,175.095 h1.78
  text "B" at -10.579,114.643 h1.78
  text "B" at 365.341,114.643 h1.78
  text "C" at -10.579,54.318 h1.78
  text "C" at 365.341,54.318 h1.78
  text "PROJECT TITLE:" at 288.125,7.048 h1.14
  text ".PRJ_Title" at 289.395,3.662 h1.78
  text "DESIGNED FOR:" at 288.125,-0.597 h1.14
  text ".PRJ_Customer" at 289.395,-4.153 h1.78
  text "D" at -10.579,-5.88 h1.78
  text "D" at 365.341,-5.88 h1.78
  text "FILE NAME:" at 288.125,-8.217 h1.14
  text ".PCB_File_Name_No_Path" at 289.395,-11.265 h1.78
  text "Texas Instruments (TI) and/or its licensors do not warrant the accuracy or completeness of this specification" at 161.9,-15.376 h1.14
  text "ENGINEER:" at 288.125,-15.583 h1.14
  text "LAYOUT BY:" at 326.352,-15.583 h1.14
  text "or any information contained therein. TI and/or its licensors do not warrant that this design will meet" at 160.757,-18.237 h1.14
  text ".PRJ_Engineer" at 289.395,-19.52 h1.78
  text ".PCB_Layout" at 327.635,-19.52 h1.78
  text "the specifications, will be suitable for your application or fit for any particular purpose, or will operate in" at 160.757,-21.099 h1.14
  text ".Layer_Name" at 14.656,-21.806 h1.52
  text "ALTIUM DESIGNER VERSION:" at 326.352,-23.457 h1.14
  text "an implementation. TI and/or its licensors do not warrant that the design is production worthy. You should" at 160.757,-23.961 h1.14
  text "completely validate and test your design implementation to confirm the system functionality for your application." at 161.9,-26.822 h1.14
  text ".print_Scale" at 289.395,-26.843 h1.78
  text ".Application_BuildNumber" at 327.635,-26.843 h1.78
  text "1" at 18.792,-32.093 h1.78
  text "2" at 82.182,-32.093 h1.78
  text "3" at 145.411,-32.093 h1.78
  text "4" at 209.08,-32.093 h1.78
  text "5" at 272.555,-32.093 h1.78
  text "6" at 336.182,-32.093 h1.78
M10 Fab Notes:
  drawing of 173 lines, arcs and shapes, not listed
  text "DESIGN INFORMATION" at 314.402,157.505 h1.52
  text "MIN. TRACK WIDTH:" at 298.03,152.933 h1.52
  text "8" at 325.874,152.933 h1.52
  text "MIL" at 329.805,152.933 h1.52
  text "MIN. CLEARANCE:" at 298.03,149.581 h1.52
  text "0.2" at 324.35,149.581 h1.52
  text "mm" at 329.805,149.581 h1.52
  text "MIN. VIA PAD SIZE:" at 298.03,146.228 h1.52
  text "24" at 325.113,146.228 h1.52
  text "MIL" at 329.805,146.228 h1.52
  text "0.05mm (2MIL)" at 315.683,142.628 h1.52
  text "MINIMUM ANNULAR RING" at 289.667,142.52 h1.52
  text "EXTERNAL" at 333.666,142.52 h1.52
  text "PER" at 294.747,139.522 h1.52
  text "IPC-D-275 CLASS 2 LEVEL C" at 300.335,139.522 h1.52
  text "MIL, HOLES" at 338.136,136.67 h1.52
  text "+/-" at 328.168,136.652 h1.52
  text "+/-" at 349.86,136.652 h1.52
  text "REGISTRATION TOLERANCES:" at 289.667,136.525 h1.52
  text "METAL" at 320.142,136.525 h1.52
  text "5" at 334.777,136.525 h1.52
  text "3" at 355.935,136.525 h1.52
  text "MIL" at 358.888,136.525 h1.52
  text "+/-" at 349.86,133.655 h1.52
  text "HOLE SIZE TOLERANCE (UNLESS OTHERWISE SPECIFIED):" at 289.667,133.528 h1.52
  text "3" at 355.935,133.528 h1.52
  text "MIL" at 358.888,133.528 h1.52
  text "MATERIAL:" at 287.768,128.208 h1.52
  text "FR-4 High Tg" at 312.824,124.643 h1.52
  text "FR-408" at 298.462,124.425 h1.52
  text "OTHER" at 336.257,124.425 h1.52
  text "X" at 308.889,124.333 h1.52
  text "62 MIL (1.6mm) +/-10%" at 306.592,120.292 h1.52
  text "THICKNESS:" at 289.667,120.184 h1.52
  text "X" at 303.337,120.184 h1.52
  text "OTHER" at 339.229,120.184 h1.52
  text "TOLERANCE:" at 289.667,116.17 h1.52
  text "X" at 310.986,116.17 h1.52
  text "ANSI IPC-6012 TYPE 3 CLASS 2" at 315.734,116.17 h1.52
  text "OTHER +/-" at 315.734,112.208 h1.52
  text "BOW & TWIST:" at 289.667,108.22 h1.52
  text "X" at 310.986,108.22 h1.52
  text "ANSI IPC-6012 TYPE 3 CLASS 2" at 315.734,108.22 h1.52
  text "OTHER +/-" at 315.734,104.194 h1.52
  text "DRILLING:" at 287.768,100.676 h1.52
  text "REFERENCE:" at 289.667,97.705 h1.52
  text "X" at 306.132,97.705 h1.52
  text "AS SHOWN" at 310.882,97.705 h1.52
  text "X" at 329.018,97.705 h1.52
  text "NC_DRILL FILES" at 332.498,97.705 h1.52
  text "PTH COPPER THICKNESS:" at 289.667,93.691 h1.52
  text "X" at 318.375,93.691 h1.52
  text "20-30 um" at 321.855,93.691 h1.52
  text "OTHER" at 340.067,93.691 h1.52
  text "BOARD FINISH:" at 287.768,89.653 h1.52
  text "SILKSCREEN:" at 291.711,86.656 h1.52
  text "X" at 315.81,86.656 h1.52
  text "TOP" at 319.01,86.656 h1.52
  text "BOTTOM" at 331.99,86.656 h1.52
  text "SILKSCREEN COLOR:" at 291.711,82.414 h1.52
  text "X" at 315.783,82.414 h1.52
  text "WHITE" at 319.01,82.414 h1.52
  text "OTHER" at 331.99,82.414 h1.52
  text "X" at 319.111,78.37 h1.52
  text "GREEN" at 322.338,78.37 h1.52
  text "OTHER" at 338.035,78.37 h1.52
  text "SOLDER RESIST COLOR:" at 291.711,78.096 h1.52
  text "X" at 319.111,74.052 h1.52
  text "MATTE" at 322.338,74.052 h1.52
  text "SEMI-GLOSS" at 338.023,74.036 h1.52
  text "IMMERSION GOLD (ENIG)" at 314.718,69.264 h1.52
  text "ENEPIG" at 348.691,69.18 h1.52
  text "SURFACE FINISH:" at 287.768,69.155 h1.52
  text "X" at 309.969,69.155 h1.52
  text "IMM. TIN/SILVER OR EQUIV" at 296.139,65.167 h1.52
  text "OTHER" at 332.498,65.167 h1.52
  text "ARRAY/PANEL:" at 287.768,60.621 h1.52
  text "CUT AND TRIM PER M1 BOARD OUTLINE" at 314.718,60.512 h1.52
  text "N.C. ROUTE" at 314.718,56.658 h1.52
  text "X" at 331.964,56.658 h1.52
  text "V. SCORE" at 336.714,56.658 h1.52
  text "CERTIFICATION:" at 287.768,53.178 h1.52
  text "MATERIALS AND WORKMANSHIP FOR ALL PCBS" at 306.183,53.178 h1.52
  text "TO MEET OR EXCEED THE REQUIREMENTS OF:" at 306.183,50.689 h1.52
  text "X" at 296.696,47.222 h1.52
  text "ANSI IPC-A-600F CLASS ->" at 300.227,47.222 h1.52
  text "X" at 341.859,47.222 h1.52
  text "2" at 344.88,47.222 h1.52
  text "1" at 336.879,47.184 h1.52
  text "3" at 353.872,47.184 h1.52
  text "X" at 317.373,43.171 h1.52
  text "RoHS" at 320.852,43.171 h1.52
  text "OTHER" at 337.22,43.171 h1.52
  text "PER ORDER" at 347.305,43.171 h1.52
  text "ALL BOARDS MUST MEET OR EXCEED UL94-V0 REQUIREMENTS." at 288.468,38.964 h1.52
  text "PCB MUST BEAR THE UL94V-0 UL REGISTERED MATERIAL ID NUMBER" at 288.468,35.916 h1.52
  text "ADDITIONAL REQUIREMENTS:" at 287.768,31.512 h1.52
  text "MICROSECTION:" at 289.667,28.591 h1.52
  text "YES" at 312.673,28.591 h1.52
  text "REQUIRED" at 334.555,24.625 h1.52
  text "BARE BOARD ELEC. TEST:" at 289.667,24.553 h1.52
  text "NONE" at 322.833,24.553 h1.52
  text "X" at 331.329,24.553 h1.52
  text "PER ORDER" at 349.592,24.553 h1.52
  text ".Layer_Name" at 14.656,-21.806 h1.52
M11 Gerber Information:
  lines w0.254: -7.417,-23.626 160.223,-23.626 ; -7.417,-18.462 160.274,-18.462 ; -7.417,-13.297 -7.417,-28.791 94.31,-28.791 160.274,-28.791 160.274,-13.297 -7.404,-13.297 -7.404,-28.791 32.614,-28.791 ; 55.194,-28.791 55.194,-13.297 ; 87.376,-18.462 87.376,-13.297 ; 108.712,-18.462 108.712,-13.297 ; 124.511,-28.956 124.511,-23.804
  text "ALL ARTWORK VIEWED FROM TOP SIDE" at -5.804,-16.654 h1.52
  text "BOARD #:" at 57.099,-16.654 h1.52
  text ".PRJ_Number" at 70.955,-16.654 h1.52
  text "REV:" at 92.405,-16.654 h1.52
  text ".PCB_Rev" at 99.809,-16.654 h1.52
  text "SVN REV:" at 113.69,-16.654 h1.52
  text ".VersionControl_RevNumber" at 126.543,-16.654 h1.52
  text "LAYER NAME =" at -5.804,-21.806 h1.52
  text "TID #:" at 57.099,-21.819 h1.52
  text ".TID" at 70.955,-21.819 h1.52
  text "PLOT NAME =" at -5.804,-27.034 h1.52
  text ".plot_File_Name" at 14.656,-27.034 h1.52
  text "GENERATED    :" at 57.15,-27.034 h1.52
  text ".Print_Date" at 79.235,-27.034 h1.52
  text ".Print_Time" at 97.752,-27.034 h1.52
  text "TEXAS INSTRUMENTS" at 129.87,-27.034 h1.52
M12 Stackup:
  drawing of 295 lines, arcs and shapes, not listed
  text "Layer" at 247.454,196.896 h1.52
  text "Name" at 257.866,196.896 h1.52
  text "Material" at 281.482,196.896 h1.52
  text "Thickness" at 303.32,196.896 h1.52
  text "Constant" at 319.826,196.896 h1.52
  text "Board Layer Stack" at 334.3,196.896 h1.52
  text "1" at 247.454,193.848 h1.52
  text "Top Overlay" at 257.866,193.848 h1.52
  text "2" at 247.454,190.8 h1.52
  text "Top Solder" at 257.866,190.8 h1.52
  text "Solder Resist" at 281.482,190.8 h1.52
  text "0,015mm" at 303.32,190.8 h1.52
  text "3,3" at 319.826,190.8 h1.52
  text "3" at 247.454,187.752 h1.52
  text "Top Layer" at 257.866,187.752 h1.52
  text "Copper" at 281.482,187.752 h1.52
  text "0,035mm" at 303.32,187.752 h1.52
  text "4" at 247.454,184.704 h1.52
  text "Dielectric1" at 257.866,184.704 h1.52
  text "FR-4" at 281.482,184.704 h1.52
  text "0,200mm" at 303.32,184.704 h1.52
  text "4,3" at 319.826,184.704 h1.52
  text "5" at 247.454,181.656 h1.52
  text "Mid Layer 1" at 257.866,181.656 h1.52
  text "Copper" at 281.482,181.656 h1.52
  text "0,035mm" at 303.32,181.656 h1.52
  text "6" at 247.454,178.608 h1.52
  text "Dielectric 2" at 257.866,178.608 h1.52
  text "FR-4" at 281.482,178.608 h1.52
  text "1,000mm" at 303.32,178.608 h1.52
  text "4,6" at 319.826,178.608 h1.52
  text "7" at 247.454,175.56 h1.52
  text "Mid Layer 2" at 257.866,175.56 h1.52
  text "Copper" at 281.482,175.56 h1.52
  text "0,035mm" at 303.32,175.56 h1.52
  text "8" at 247.454,172.512 h1.52
  text "Dielectric 3" at 257.866,172.512 h1.52
  text "FR-4" at 281.482,172.512 h1.52
  text "0,200mm" at 303.32,172.512 h1.52
  text "4,3" at 319.826,172.512 h1.52
  text "9" at 247.454,169.464 h1.52
  text "Bottom Layer" at 257.866,169.464 h1.52
  text "Copper" at 281.482,169.464 h1.52
  text "0,035mm" at 303.32,169.464 h1.52
  text "10" at 247.454,166.416 h1.52
  text "Bottom Solder" at 257.866,166.416 h1.52
  text "Solder Resist" at 281.482,166.416 h1.52
  text "0,015mm" at 303.32,166.416 h1.52
  text "3,3" at 319.826,166.416 h1.52
  text "11" at 247.454,163.368 h1.52
  text "Bottom Overlay" at 257.866,163.368 h1.52
  text ".Layer_Name" at 14.656,-21.806 h1.52
M13 Component Bodies Top:
  text ".Layer_Name" at 14.656,-21.806 h1.52
M14 Component Bodies Bottom:
  text ".Layer_Name" at 14.656,-21.806 h1.52
M15 Courtyards Top:
  text ".Layer_Name" at 14.656,-21.806 h1.52
M16 Courtyards Bottom:
  text ".Layer_Name" at 14.656,-21.806 h1.52
Drill Drawing:
  drawing of 152 lines, arcs and shapes, not listed
  text "Symbol" at 135.783,85.859 h1.83
  text "Quantity" at 143.041,85.859 h1.83
  text "Finished Hole Size" at 151.097,85.859 h1.83
  text "Plated" at 166.889,85.859 h1.83
  text "Hole Type" at 173.095,85.859 h1.83
  text "Drill Layer Pair" at 182.248,85.859 h1.83
  text "Hole Tolerance" at 200.269,85.859 h1.83
  text "134" at 143.041,83.328 h1.52
  text "7,87mil (0,200mm)" at 151.097,83.328 h1.52
  text "PTH" at 166.889,83.328 h1.52
  text "Round" at 173.095,83.328 h1.52
  text "Top Layer - Bottom Layer" at 182.248,83.328 h1.52
  text "12" at 143.041,80.798 h1.52
  text "11,81mil (0,300mm)" at 151.097,80.798 h1.52
  text "PTH" at 166.889,80.798 h1.52
  text "Round" at 173.095,80.798 h1.52
  text "Top Layer - Bottom Layer" at 182.248,80.798 h1.52
  text "15" at 143.041,78.267 h1.52
  text "12,00mil (0,305mm)" at 151.097,78.267 h1.52
  text "PTH" at 166.889,78.267 h1.52
  text "Round" at 173.095,78.267 h1.52
  text "Top Layer - Bottom Layer" at 182.248,78.267 h1.52
  text "6" at 143.041,75.737 h1.52
  text "19,69mil (0,500mm)" at 151.097,75.737 h1.52
  text "PTH" at 166.889,75.737 h1.52
  text "Round" at 173.095,75.737 h1.52
  text "Top Layer - Bottom Layer" at 182.248,75.737 h1.52
  text "2" at 143.041,73.207 h1.52
  text "27,56mil (0,700mm)" at 151.097,73.207 h1.52
  text "PTH" at 166.889,73.207 h1.52
  text "Round" at 173.095,73.207 h1.52
  text "Top Layer - Bottom Layer" at 182.248,73.207 h1.52
  text "4" at 143.041,70.676 h1.52
  text "39,37mil (1,000mm)" at 151.097,70.676 h1.52
  text "PTH" at 166.889,70.676 h1.52
  text "Round" at 173.095,70.676 h1.52
  text "Top Layer - Bottom Layer" at 182.248,70.676 h1.52
  text "9" at 143.041,68.146 h1.52
  text "40,00mil (1,016mm)" at 151.097,68.146 h1.52
  text "PTH" at 166.889,68.146 h1.52
  text "Round" at 173.095,68.146 h1.52
  text "Top Layer - Bottom Layer" at 182.248,68.146 h1.52
  text "6" at 143.041,65.615 h1.52
  text "40,16mil (1,020mm)" at 151.097,65.615 h1.52
  text "PTH" at 166.889,65.615 h1.52
  text "Round" at 173.095,65.615 h1.52
  text "Top Layer - Bottom Layer" at 182.248,65.615 h1.52
  text "24" at 143.041,63.085 h1.52
  text "43,31mil (1,100mm)" at 151.097,63.085 h1.52
  text "PTH" at 166.889,63.085 h1.52
  text "Round" at 173.095,63.085 h1.52
  text "Top Layer - Bottom Layer" at 182.248,63.085 h1.52
  text "2" at 143.041,60.555 h1.52
  text "47,24mil (1,200mm)" at 151.097,60.555 h1.52
  text "PTH" at 166.889,60.555 h1.52
  text "Round" at 173.095,60.555 h1.52
  text "Top Layer - Bottom Layer" at 182.248,60.555 h1.52
  text "4" at 143.041,58.024 h1.52
  text "51,18mil (1,300mm)" at 151.097,58.024 h1.52
  text "PTH" at 166.889,58.024 h1.52
  text "Round" at 173.095,58.024 h1.52
  text "Top Layer - Bottom Layer" at 182.248,58.024 h1.52
  text "6" at 143.041,55.494 h1.52
  text "64,96mil (1,650mm)" at 151.097,55.494 h1.52
  text "PTH" at 166.889,55.494 h1.52
  text "Round" at 173.095,55.494 h1.52
  text "Top Layer - Bottom Layer" at 182.248,55.494 h1.52
  text "2" at 143.041,52.963 h1.52
  text "118,11mil (3,000mm)" at 151.097,52.963 h1.52
  text "PTH" at 166.889,52.963 h1.52
  text "Round" at 173.095,52.963 h1.52
  text "Top Layer - Bottom Layer" at 182.248,52.963 h1.52
  text "1" at 143.041,50.433 h1.52
  text "137,80mil (3,500mm)" at 151.097,50.433 h1.52
  text "PTH" at 166.889,50.433 h1.52
  text "Round" at 173.095,50.433 h1.52
  text "Top Layer - Bottom Layer" at 182.248,50.433 h1.52
  text "227 Total" at 143.041,47.903 h1.52
  text ".Layer_Name" at 14.656,-21.806 h1.52
M17 Embedded Cavity:
  text ".Layer_Name" at 14.656,-21.806 h1.52
M18 Embedded Assembly:
  text ".Layer_Name" at 14.656,-21.806 h1.52
M19 Embedded Keepout:
  text ".Layer_Name" at 14.656,-21.806 h1.52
